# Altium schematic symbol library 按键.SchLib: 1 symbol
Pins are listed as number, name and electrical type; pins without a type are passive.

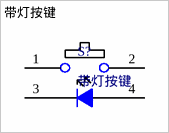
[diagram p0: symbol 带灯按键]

## 带灯按键
designator S?
https://item.taobao.com/item.htm?id=677075017698
footprint 带灯按键
pins: 1, 2, 3, 4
